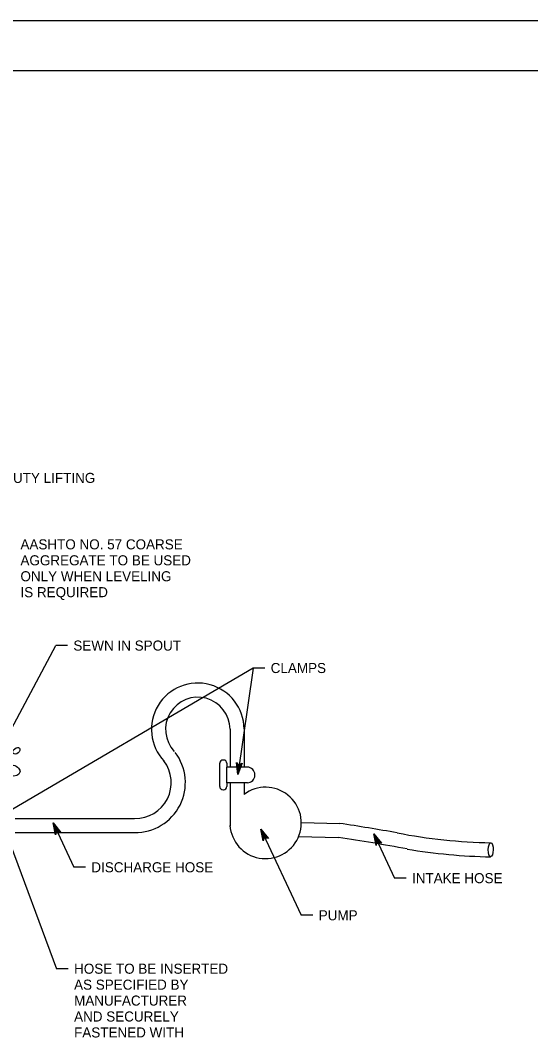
# Model space of a CAD drawing. Extents: x 636462 to 637367, y 299944 to 300538.
# Drawn here: x 636883.5 to 637035.5, y 300234.4 to 300538.4 of the extents above; entities that cross this region are included whole.
import ezdxf

# ---------------------------------------------------------------- set-up
doc = ezdxf.new("R2010")
doc.units = 0
for name, color, linetype in [('1', 7, 'Continuous'), ('Default', 7, 'Continuous'), ('PLT-BNDY', 7, 'Continuous')]:
    doc.layers.add(name, color=color, linetype=linetype)

msp = doc.modelspace()

# ---------------------------------------------------------------- linework, layer by layer
at = {"layer": '1'}
msp.add_lwpolyline([(637287.91, 299959.45), (637287.91, 300523.45), (636501.91, 300523.45), (636501.91, 299959.45), (637287.91, 299959.45), (637287.91, 299985.81), (637087.91, 299985.81), (637087.91, 300050.49), (637287.91, 300050.49), (637287.91, 300079.45), (637087.91, 300079.45), (637087.91, 299959.45), (637166.72, 299959.45), (637166.72, 299985.81), (637166.72, 299959.45), (637243.72, 299959.45), (637243.72, 299985.81), (637243.72, 299973.49), (637287.91, 299973.49)], dxfattribs=at)
at = {"layer": 'Default'}
for p, q in [((636865.7, 300299.03), (636894.03, 300352.14)), ((636897.52, 300352.14), (636894.03, 300352.14)), ((636952.82, 300345.46), (636872.15, 300298.08)), ((636952.82, 300345.46), (636948.27, 300313.74)), ((636956.31, 300345.46), (636952.82, 300345.46)), ((636945.94, 300327.26), (636945.94, 300315.92)), ((636950.13, 300327.26), (636950.13, 300315.92)), ((636942.87, 300310.11), (636942.87, 300317.07)), ((636944.95, 300317.07), (636944.95, 300315.92)), ((636944.95, 300311.26), (636944.95, 300315.92)), ((636951.1, 300315.92), (636944.95, 300315.92)), ((636944.95, 300311.26), (636944.95, 300310.11)), ((636951.1, 300311.26), (636944.95, 300311.26)), ((636945.94, 300311.26), (636945.94, 300298.36)), ((636950.13, 300311.26), (636950.13, 300307.8)), ((636881.89, 300300.65), (636917.52, 300300.65)), ((636893.22, 300299.29), (636899.38, 300286.08)), ((636967.18, 300299.44), (636978.62, 300299.16)), ((636879.41, 300295.76), (636894.23, 300255.85)), ((636881.89, 300296.45), (636917.52, 300296.45)), ((636955.15, 300297.48), (636967.12, 300271.77)), ((636966.39, 300295.26), (636978.25, 300294.97)), ((636988.76, 300296.06), (636994.92, 300282.84)), ((636902.87, 300286.08), (636899.38, 300286.08)), ((636998.42, 300282.84), (636994.92, 300282.84)), ((636970.62, 300271.77), (636967.12, 300271.77)), ((636897.73, 300255.85), (636894.23, 300255.85))]:
    msp.add_line(p, q, dxfattribs=at)
for points in [[(636949.31, 300316.86), (636949.57, 300317.1), (636948.27, 300313.74), (636949.31, 300316.86), (636948.91, 300316.71), (636948.27, 300313.74), (636948.39, 300316.77), (636948.05, 300317), (636948.27, 300313.74), (636947.83, 300317.32), (636948.05, 300317)], [(636893.99, 300296.09), (636893.9, 300295.75), (636893.22, 300299.29), (636893.99, 300296.09), (636894.25, 300296.43), (636893.22, 300299.29), (636894.72, 300296.65), (636895.14, 300296.64), (636893.22, 300299.29), (636895.48, 300296.49), (636895.14, 300296.64)], [(636955.92, 300294.27), (636955.83, 300293.93), (636955.15, 300297.48), (636955.92, 300294.27), (636956.17, 300294.61), (636955.15, 300297.48), (636956.65, 300294.83), (636957.06, 300294.82), (636955.15, 300297.48), (636957.41, 300294.67), (636957.06, 300294.82)], [(636989.53, 300292.85), (636989.44, 300292.52), (636988.76, 300296.06), (636989.53, 300292.85), (636989.79, 300293.19), (636988.76, 300296.06), (636990.26, 300293.41), (636990.68, 300293.4), (636988.76, 300296.06), (636991.03, 300293.25), (636990.68, 300293.4)]]:
    msp.add_lwpolyline(points, dxfattribs=at)
for centre, radius, start, end in [((636936.34, 300327.17), 13.8, 0.5613, 222.9646), ((636936.34, 300327.17), 9.6, 0.5613, 222.9646), ((636917.8, 300311.29), 14.84, 268.9361, 37.4861), ((636917.79, 300311.29), 10.64, 268.54, 37.4749), ((636943.85, 300317.07), 0.974, 90, 180), ((636943.97, 300317.07), 0.974, 360, 90), ((636951.1, 300313.67), 2.25, 360, 90), ((636951.1, 300313.51), 2.25, 270, 360), ((636943.85, 300310.11), 0.974, 180, 270), ((636943.97, 300310.11), 0.974, 270, 0), ((636956.54, 300299.3), 10.64, 183.9748, 127.0016), ((636882.55, 299663.96), 642.42, 79.84955, 81.40009), ((637026.53, 300454.94), 161.57, 259.024, 268.9844), ((636882.55, 299663.96), 638.23, 79.51504, 81.37638), ((637026.53, 300454.94), 165.77, 260.3328, 268.9844)]:
    msp.add_arc(centre, radius, start, end, dxfattribs=at)
for centre, major_axis, ratio in [((636882.29, 300320.79), (0.938, 0.766), 0.672414), ((636880.99, 300314.93), (-2.36, 0.55), 0.672414), ((637023.63, 300291.3), (-0.04, -2.1), 0.344138)]:
    msp.add_ellipse(centre, major_axis=major_axis, ratio=ratio, dxfattribs=at)
at = {"layer": 'PLT-BNDY'}
msp.add_lwpolyline([(636461.91, 300538.45), (637302.91, 300538.45), (637302.91, 299944.45), (636461.91, 299944.45)], close=True, dxfattribs=at)

# ---------------------------------------------------------------- texts
at = {"layer": 'Default'}
for s, p in [('HEAVY DUTY LIFTING', (636863.69, 300400.62)), ('AASHTO NO. 57 COARSE', (636883.5, 300380.81)), ('AGGREGATE TO BE USED', (636883.5, 300376.06)), ('ONLY WHEN LEVELING', (636883.5, 300371.31)), ('IS REQUIRED', (636883.5, 300366.56)), ('SEWN IN SPOUT', (636899.27, 300350.65)), ('CLAMPS', (636958.06, 300343.96)), ('DISCHARGE HOSE', (636904.62, 300284.58)), ('INTAKE HOSE', (637000.17, 300281.34)), ('PUMP', (636972.37, 300270.27)), ('HOSE TO BE INSERTED', (636899.48, 300254.35)), ('AS SPECIFIED BY', (636899.48, 300249.6)), ('MANUFACTURER', (636899.48, 300244.86)), ('AND SECURELY', (636899.48, 300240.11)), ('FASTENED WITH', (636899.48, 300235.36))]:
    msp.add_text(s, height=2.998, dxfattribs=at).set_placement(p)

doc.saveas('drawing.dxf')
